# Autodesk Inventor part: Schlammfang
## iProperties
Created: 2009-02
Part Number: Schlammfang
Document SubType Name: Blech
Designer: Strathkötter
Density: 1 g/cm^3
Author: Strathkötter
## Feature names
1. Extrusion2
2. Extrusion3
3. Runde Anordnung1 [Circular Pattern]
